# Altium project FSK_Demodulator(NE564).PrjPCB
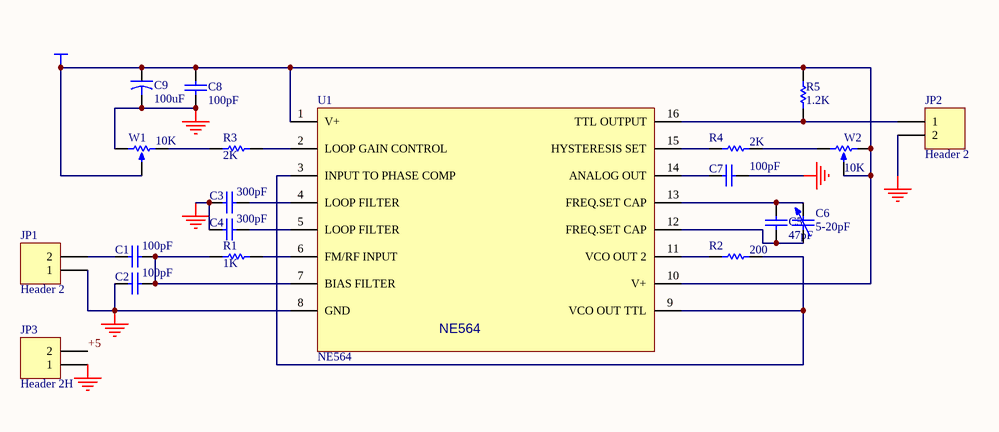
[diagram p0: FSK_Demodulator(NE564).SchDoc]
1 sheet, 20 parts. Net scope: global (net labels, ports and power ports of the same name join across sheets).
Board file: FSK_Demodulator(NE564).PcbDoc

## Sheet FSK_Demodulator(NE564).SchDoc
size B

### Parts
C1  100pF  [CC2012-0805]
C2  100pF  [CC2012-0805]
C3  300pF  [CC2012-0805]
C4  300pF  [CC2012-0805]
C5  47pF  [CC2012-0805]
C6  5-20pF  [C3225-1210]
C7  100pF  [CC2012-0805]
C8  100pF  [CC2012-0805]
C9  100uF  [CAPR5-4X5]
JP1  Header 2  [HDR1X2]
JP2  Header 2  [HDR1X2]
JP3  Header 2H  [HDR1X2H]
R1  1K  [R2012-0805]
R2  200  [CC2012-0805]
R3  2K  [R2012-0805]
R4  2K  [CC2012-0805]
R5  1.2K  [CC2012-0805]
U1  NE564  [DIP-16]
W1  10K  [VR5]
W2  10K  [VR5]

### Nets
+5: C8.2 C9.1 JP3.2 R5.2 U1.1(V+) U1.10(V+) W1.3(TAP) W2.2(BOT) W2.3(TAP)
GND: C2.1 C3.1 C4.1 C7.2 C8.1 C9.2 JP1.1 JP2.2 JP3.1 U1.8(GND) W1.1(TOP)
NetC1_1: C1.1 JP1.2
NetC1_2: C1.2 C2.2 R1.1 U1.7(BIAS_FILTER)
NetC3_2: C3.2 U1.4(LOOP_FILTER)
NetC4_2: C4.2 U1.5(LOOP_FILTER)
NetC5_1: C5.1 C6.1 U1.12(FREQ.SET_CAP)
NetC5_2: C5.2 C6.2 U1.13(FREQ.SET_CAP)
NetC7_1: C7.1 U1.14(ANALOG_OUT)
NetJP2_1: JP2.1 R5.1 U1.16(TTL_OUTPUT)
NetR1_2: R1.2 U1.6(FM/RF_INPUT)
NetR2_1: R2.1 U1.11(VCO_OUT_2)
NetR2_2: R2.2 U1.3(INPUT_TO_PHASE_COMP) U1.9(VCO_OUT_TTL)
NetR3_1: R3.1 W1.2(BOT)
NetR3_2: R3.2 U1.2(LOOP_GAIN_CONTROL)
NetR4_1: R4.1 U1.15(HYSTERESIS_SET)
NetR4_2: R4.2 W2.1(TOP)

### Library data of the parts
C1-C5 C7 C8 = Cap: Capacitor; Manufacturer: Generic Components; Class I: Passive
C6 = Cap Var: Variable or Adjustable Capacitor; Manufacturer: Generic Components; Class I: Passive
C9 = Cap2: Capacitor; Manufacturer: Generic Components; Class I: Passive
JP1 JP2 = Header 2: Header, 2-Pin; Manufacturer: Generic Components; Class I: Connector
JP3 = Header 2H: Header, 2-Pin,  Right Angle; Manufacturer: Generic Components; Class I: Connector
R1-R5 = Res1: Resistor; Manufacturer: Generic Components; Class I: Passive
U1 = NE564: Manufacturer: Philips; Class 1: PLL&DDS; Class 2: Phase Lock Loop
W1 W2 = RPot1: Potentiometer; Manufacturer: Generic Components; Class I: Passive; Set Position: 0.5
